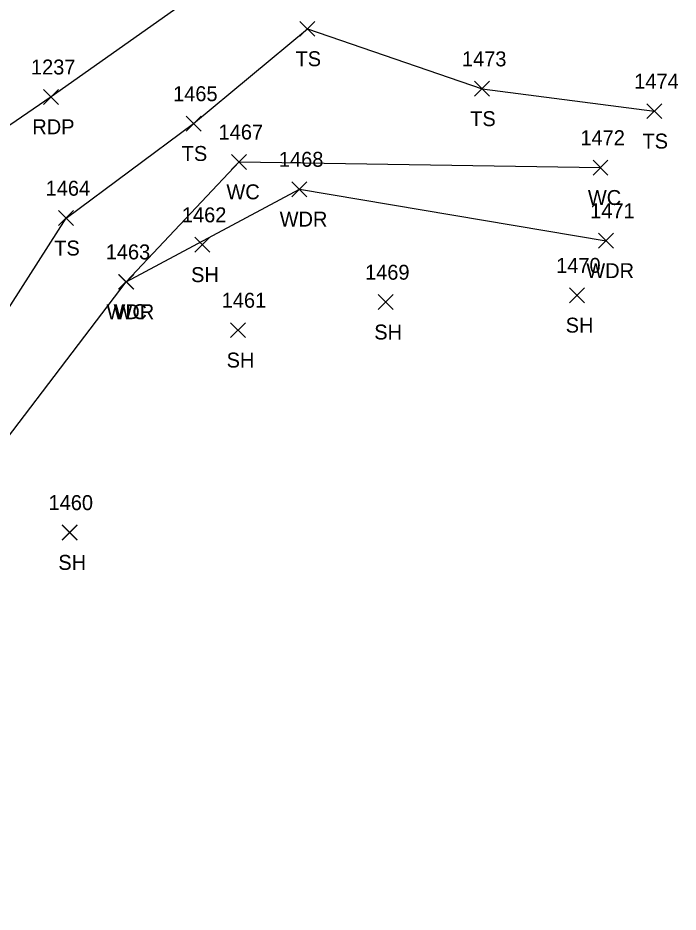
# Model space of a CAD drawing. Extents: x 1528286 to 1556263, y 492387 to 508952.
# Drawn here: x 1529115 to 1529203.3, y 492980.3 to 493100 of the extents above; entities that cross this region are included whole.
import ezdxf

# ---------------------------------------------------------------- set-up
doc = ezdxf.new("R2010")
doc.units = 0
for name, color, linetype in [('L_A', 7, 'Continuous'), ('L_I', 7, 'Continuous'), ('L_TIC', 7, 'Continuous'), ('LAWA', 7, 'Continuous'), ('LAWE', 7, 'Continuous'), ('LELB', 7, 'Continuous'), ('P_A', 7, 'Continuous'), ('P_I', 7, 'Continuous'), ('P_TIC', 7, 'Continuous'), ('PET', 7, 'Continuous')]:
    doc.layers.add(name, color=color, linetype=linetype)

msp = doc.modelspace()

# ---------------------------------------------------------------- linework, layer by layer
at = {"layer": 'L_TIC'}
for points in [[(1529152.74, 493097.53), (1529154.74, 493099.53)], [(1529154.74, 493097.53), (1529152.74, 493099.53)], [(1529152.74, 493097.53), (1529154.74, 493099.53)], [(1529154.74, 493097.53), (1529152.74, 493099.53)], [(1529176.1, 493089.51), (1529178.1, 493091.51)], [(1529178.1, 493089.51), (1529176.1, 493091.51)], [(1529176.1, 493089.51), (1529178.1, 493091.51)], [(1529178.1, 493089.51), (1529176.1, 493091.51)], [(1529199.14, 493086.51), (1529201.14, 493088.51)], [(1529201.14, 493086.51), (1529199.14, 493088.51)], [(1529199.14, 493086.51), (1529201.14, 493088.51)], [(1529201.14, 493086.51), (1529199.14, 493088.51)], [(1529137.52, 493084.85), (1529139.52, 493086.85)], [(1529139.52, 493084.85), (1529137.52, 493086.85)], [(1529137.52, 493084.85), (1529139.52, 493086.85)], [(1529139.52, 493084.85), (1529137.52, 493086.85)], [(1529143.6, 493079.72), (1529145.6, 493081.72)], [(1529145.6, 493079.72), (1529143.6, 493081.72)], [(1529143.61, 493079.72), (1529145.61, 493081.72)], [(1529145.61, 493079.72), (1529143.61, 493081.72)], [(1529191.94, 493078.96), (1529193.94, 493080.96)], [(1529193.94, 493078.96), (1529191.94, 493080.96)], [(1529191.94, 493078.96), (1529193.94, 493080.96)], [(1529193.94, 493078.96), (1529191.94, 493080.96)], [(1529151.67, 493076.07), (1529153.67, 493078.07)], [(1529153.67, 493076.07), (1529151.67, 493078.07)], [(1529151.67, 493076.07), (1529153.67, 493078.07)], [(1529153.67, 493076.07), (1529151.67, 493078.07)], [(1529120.47, 493072.2), (1529122.47, 493074.2)], [(1529122.47, 493072.2), (1529120.47, 493074.2)], [(1529120.47, 493072.2), (1529122.47, 493074.2)], [(1529122.47, 493072.2), (1529120.47, 493074.2)], [(1529138.69, 493068.64), (1529140.69, 493070.64)], [(1529140.69, 493068.64), (1529138.69, 493070.64)], [(1529138.7, 493068.64), (1529140.7, 493070.64)], [(1529140.7, 493068.64), (1529138.7, 493070.64)], [(1529192.68, 493069.17), (1529194.68, 493071.17)], [(1529194.68, 493069.17), (1529192.68, 493071.17)], [(1529192.68, 493069.17), (1529194.68, 493071.17)], [(1529194.68, 493069.17), (1529192.68, 493071.17)], [(1529128.5, 493063.68), (1529130.5, 493065.68)], [(1529130.5, 493063.68), (1529128.5, 493065.68)], [(1529128.5, 493063.68), (1529130.5, 493065.68)], [(1529130.5, 493063.68), (1529128.5, 493065.68)], [(1529128.51, 493063.68), (1529130.51, 493065.68)], [(1529130.51, 493063.68), (1529128.51, 493065.68)], [(1529128.51, 493063.68), (1529130.51, 493065.68)], [(1529130.51, 493063.68), (1529128.51, 493065.68)], [(1529188.79, 493061.88), (1529190.79, 493063.88)], [(1529190.79, 493061.88), (1529188.79, 493063.88)], [(1529188.79, 493061.88), (1529190.79, 493063.88)], [(1529190.79, 493061.88), (1529188.79, 493063.88)], [(1529163.2, 493060.96), (1529165.2, 493062.96)], [(1529165.2, 493060.96), (1529163.2, 493062.96)], [(1529163.2, 493060.96), (1529165.2, 493062.96)], [(1529165.2, 493060.96), (1529163.2, 493062.96)], [(1529143.45, 493057.21), (1529145.45, 493059.21)], [(1529145.45, 493057.21), (1529143.45, 493059.21)], [(1529143.45, 493057.21), (1529145.45, 493059.21)], [(1529145.45, 493057.21), (1529143.45, 493059.21)], [(1529120.94, 493030.13), (1529122.94, 493032.13)], [(1529122.94, 493030.13), (1529120.94, 493032.13)], [(1529120.95, 493030.14), (1529122.95, 493032.14)], [(1529122.95, 493030.14), (1529120.95, 493032.14)]]:
    msp.add_lwpolyline(points, dxfattribs=at)
at = {"layer": 'LAWA'}
for points in [[(1529047.22, 492980.34), (1529070.46, 492998.89), (1529105.52, 493033.17), (1529129.51, 493064.68), (1529152.67, 493077.07), (1529193.68, 493070.17)], [(1529047.22, 492980.34), (1529070.46, 492998.89), (1529105.52, 493033.17), (1529129.5, 493064.68), (1529152.67, 493077.07), (1529193.68, 493070.17)]]:
    msp.add_lwpolyline(points, dxfattribs=at)
at = {"layer": 'LAWE'}
for points in [[(1529048.19, 492983.65), (1529070.46, 492998.89), (1529105.52, 493033.17), (1529129.51, 493064.68), (1529144.61, 493080.72), (1529192.94, 493079.96)], [(1529048.19, 492983.65), (1529070.46, 492998.89), (1529105.52, 493033.17), (1529129.5, 493064.68), (1529144.6, 493080.72), (1529192.94, 493079.96)]]:
    msp.add_lwpolyline(points, dxfattribs=at)
at = {"layer": 'LELB'}
for points in [[(1529059.99, 492996.69), (1529077.46, 493012.97), (1529080.57, 493024.46), (1529069.82, 493035.21), (1529086.02, 493051.77), (1529100.55, 493040.52), (1529121.47, 493073.2), (1529138.52, 493085.85), (1529153.74, 493098.53), (1529177.1, 493090.51), (1529200.14, 493087.51)], [(1529059.99, 492996.69), (1529077.45, 493012.96), (1529080.57, 493024.46), (1529069.82, 493035.21), (1529086.02, 493051.77), (1529100.55, 493040.52), (1529121.47, 493073.2), (1529138.52, 493085.85), (1529153.74, 493098.53), (1529177.1, 493090.51), (1529200.14, 493087.51)]]:
    msp.add_lwpolyline(points, dxfattribs=at)
at = {"layer": 'P_TIC'}
for points in [[(1529118.46, 493088.42), (1529120.46, 493090.42)], [(1529120.46, 493088.42), (1529118.46, 493090.42)], [(1529118.46, 493088.42), (1529120.46, 493090.42)], [(1529120.46, 493088.42), (1529118.46, 493090.42)]]:
    msp.add_lwpolyline(points, dxfattribs=at)
at = {"layer": 'PET'}
msp.add_lwpolyline([(1528981.67, 493029.84), (1529023.32, 493058.68), (1529062.76, 493086.59), (1529101.46, 493113.53), (1529137.06, 493138.01), (1529145.3, 493125.26), (1529153.7, 493113.65), (1529119.46, 493089.42), (1529079.43, 493062), (1529041.27, 493034), (1528999.91, 493006.62)], dxfattribs=at)
msp.add_lwpolyline([(1528981.67, 493029.84), (1529023.32, 493058.68), (1529062.76, 493086.59), (1529101.46, 493113.53), (1529137.06, 493138.01), (1529145.3, 493125.26), (1529153.7, 493113.65), (1529119.46, 493089.42), (1529079.43, 493062), (1529041.27, 493034), (1528999.91, 493006.62)], dxfattribs=at)

# ---------------------------------------------------------------- texts
at = {"layer": 'L_A'}
for s, p in [('TS', (1529152.15, 493093.53)), ('TS', (1529152.15, 493093.53)), ('TS', (1529175.51, 493085.51)), ('TS', (1529175.51, 493085.51)), ('TS', (1529198.55, 493082.51)), ('TS', (1529198.55, 493082.51)), ('TS', (1529136.93, 493080.85)), ('TS', (1529136.93, 493080.85)), ('WC', (1529142.91, 493075.72)), ('WC', (1529142.91, 493075.72)), ('WC', (1529191.25, 493074.96)), ('WC', (1529191.25, 493074.96)), ('WDR', (1529150.03, 493072.07)), ('WDR', (1529150.03, 493072.07)), ('TS', (1529119.88, 493068.2)), ('TS', (1529119.88, 493068.2)), ('WDR', (1529191.04, 493065.17)), ('WDR', (1529191.04, 493065.17)), ('SH', (1529138.18, 493064.64)), ('SH', (1529138.19, 493064.64)), ('WDR', (1529126.87, 493059.68)), ('WDR', (1529126.87, 493059.68)), ('WC', (1529127.81, 493059.68)), ('WC', (1529127.82, 493059.68)), ('SH', (1529188.28, 493057.88)), ('SH', (1529188.28, 493057.88)), ('SH', (1529162.68, 493056.96)), ('SH', (1529162.69, 493056.96)), ('SH', (1529142.94, 493053.21)), ('SH', (1529142.94, 493053.21)), ('SH', (1529120.43, 493026.13)), ('SH', (1529120.43, 493026.14))]:
    msp.add_text(s, height=2, dxfattribs=at).set_placement(p)
at = {"layer": 'L_I'}
for s, p in [('1473', (1529174.41, 493093.51)), ('1473', (1529174.41, 493093.51)), ('1474', (1529197.45, 493090.51)), ('1474', (1529197.45, 493090.51)), ('1465', (1529135.78, 493088.85)), ('1465', (1529135.78, 493088.85)), ('1467', (1529141.87, 493083.72)), ('1467', (1529141.86, 493083.72)), ('1472', (1529190.25, 493082.96)), ('1472', (1529190.25, 493082.96)), ('1468', (1529149.93, 493080.07)), ('1468', (1529149.93, 493080.07)), ('1464', (1529118.73, 493076.2)), ('1464', (1529118.73, 493076.2)), ('1471', (1529191.56, 493073.17)), ('1471', (1529191.55, 493073.17)), ('1462', (1529136.96, 493072.64)), ('1462', (1529136.95, 493072.64)), ('1463', (1529126.77, 493067.68)), ('1463', (1529126.77, 493067.68)), ('1463', (1529126.76, 493067.68)), ('1463', (1529126.76, 493067.68)), ('1470', (1529187.01, 493065.88)), ('1470', (1529187.01, 493065.88)), ('1469', (1529161.45, 493064.96)), ('1469', (1529161.45, 493064.96)), ('1461', (1529142.28, 493061.21)), ('1461', (1529142.28, 493061.21)), ('1460', (1529119.12, 493034.14)), ('1460', (1529119.12, 493034.13))]:
    msp.add_text(s, height=2, dxfattribs=at).set_placement(p)
at = {"layer": 'P_A'}
msp.add_text('RDP', height=2, dxfattribs=at).set_placement((1529116.95, 493084.42))
msp.add_text('RDP', height=2, dxfattribs=at).set_placement((1529116.95, 493084.42))
at = {"layer": 'P_I'}
msp.add_text('1237', height=2, dxfattribs=at).set_placement((1529116.77, 493092.42))
msp.add_text('1237', height=2, dxfattribs=at).set_placement((1529116.77, 493092.42))

doc.saveas('drawing.dxf')
